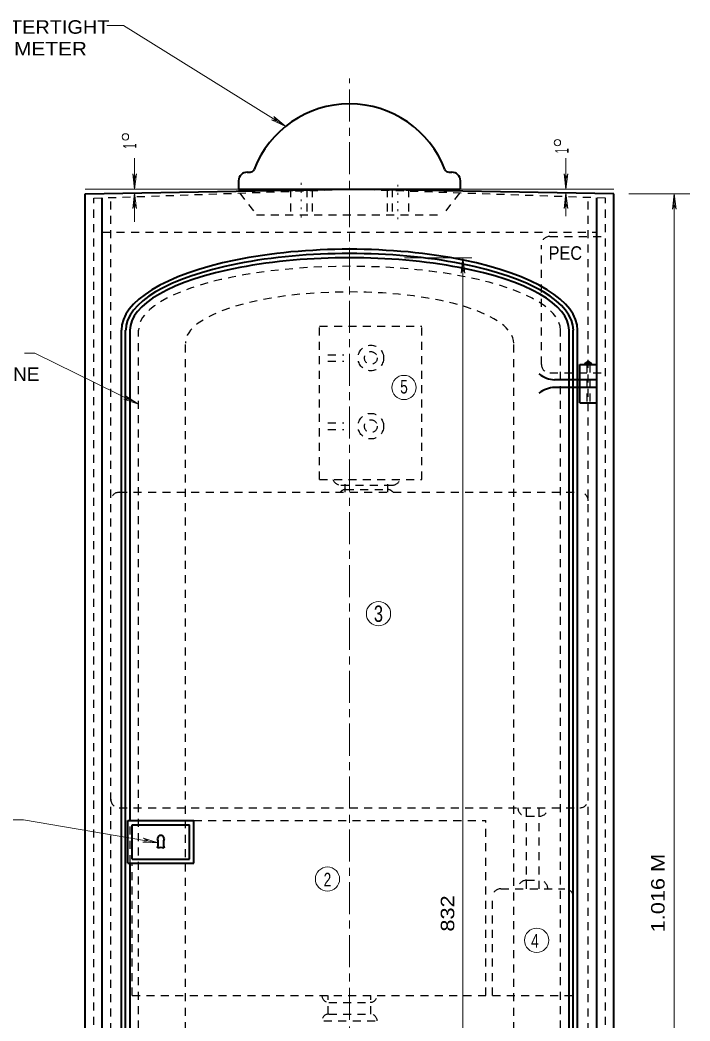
# Model space of a CAD drawing. Extents: x 312583 to 312853, y 144419 to 144586.
# Drawn here: x 312634.8 to 312672.5, y 144473.4 to 144529.6 of the extents above; entities that cross this region are included whole.
import ezdxf
from ezdxf.enums import TextEntityAlignment as Align

# ---------------------------------------------------------------- set-up
doc = ezdxf.new("R2010")
doc.units = 0
doc.header["$LTSCALE"] = 0.3
for name, pattern in [('DOTTED', [1.5, 0.3, -1.2]), ('LONG_DASH_SHORT_DASH', [9.9, 6, -1.2, 1.5, -1.2]), ('SHORT_DASHED', [2.7, 1.5, -1.2])]:
    doc.linetypes.add(name, pattern=pattern)
doc.layers.add('1', color=7, linetype='Continuous', lineweight=13)

msp = doc.modelspace()

# ---------------------------------------------------------------- linework, layer by layer
at = {"layer": '1', "linetype": 'LONG_DASH_SHORT_DASH'}
msp.add_line((312653.3356, 144440.7591), (312653.3356, 144526.3344), dxfattribs=at)
at = {"layer": '1'}
for p, q in [((312649.0729, 144524.1954), (312649.2493, 144523.9578)), ((312649.7476, 144523.6434), (312649.0729, 144524.1954)), ((312648.9579, 144524.0114), (312649.2493, 144523.9578)), ((312649.7476, 144523.6434), (312648.9579, 144524.0114)), ((312641.2606, 144520.1091), (312641.2606, 144521.8571)), ((312665.4949, 144520.1091), (312665.4949, 144521.8571)), ((312641.1533, 144520.9754), (312641.2606, 144520.6994)), ((312641.2606, 144520.1091), (312641.1533, 144520.9754)), ((312641.3679, 144520.9754), (312641.2606, 144520.6994)), ((312641.2606, 144520.1091), (312641.3679, 144520.9754)), ((312665.3876, 144520.9754), (312665.4949, 144520.6994)), ((312665.4949, 144520.1091), (312665.3876, 144520.9754)), ((312665.6023, 144520.9754), (312665.4949, 144520.6994)), ((312665.4949, 144520.1091), (312665.6023, 144520.9754)), ((312653.3356, 144520.1091), (312638.4776, 144520.1091)), ((312641.2606, 144519.8944), (312641.1533, 144519.0281)), ((312641.2606, 144518.2768), (312641.2606, 144519.8944)), ((312641.2606, 144519.8944), (312641.3679, 144519.0281)), ((312653.3356, 144520.1091), (312668.1859, 144520.1091)), ((312665.4949, 144519.8944), (312665.3876, 144519.0281)), ((312665.4949, 144518.5911), (312665.4949, 144519.8944)), ((312665.4949, 144519.8944), (312665.6023, 144519.0281)), ((312669.0369, 144519.8484), (312672.4653, 144519.8484)), ((312671.5823, 144519.8484), (312671.475, 144518.9821)), ((312671.5823, 144443.1818), (312671.5823, 144519.8484)), ((312671.5823, 144519.8484), (312671.6897, 144518.9821)), ((312641.1533, 144519.0281), (312641.2606, 144519.3041)), ((312641.3679, 144519.0281), (312641.2606, 144519.3041)), ((312665.3876, 144519.0281), (312665.4949, 144519.3041)), ((312665.6023, 144519.0281), (312665.4949, 144519.3041)), ((312671.475, 144518.9821), (312671.5823, 144519.2581)), ((312671.6897, 144518.9821), (312671.5823, 144519.2581)), ((312656.4329, 144516.2528), (312660.2049, 144516.2528)), ((312659.7066, 144516.2528), (312659.5993, 144515.3864)), ((312659.7066, 144462.9541), (312659.7066, 144516.2528)), ((312659.7066, 144516.2528), (312659.8139, 144515.3864)), ((312659.5993, 144515.3864), (312659.7066, 144515.6624)), ((312659.8139, 144515.3864), (312659.7066, 144515.6624)), ((312635.6486, 144510.8938), (312635.0712, 144510.8938)), ((312641.4753, 144508.0264), (312635.6486, 144510.8938)), ((312640.6549, 144508.3178), (312640.9463, 144508.2871)), ((312641.4753, 144508.0264), (312640.6549, 144508.3178)), ((312640.7469, 144508.5094), (312640.9463, 144508.2871)), ((312641.4753, 144508.0264), (312640.7469, 144508.5094)), ((312635.0199, 144484.6814), (312633.7017, 144484.6814)), ((312642.5869, 144483.3858), (312635.0199, 144484.6814)), ((312641.7513, 144483.6388), (312642.0043, 144483.4854)), ((312642.5869, 144483.3858), (312641.7513, 144483.6388)), ((312641.7206, 144483.4241), (312642.0043, 144483.4854)), ((312642.5869, 144483.3858), (312641.7206, 144483.4241))]:
    msp.add_line(p, q, dxfattribs=at)
at = {"layer": '1', "lineweight": 40}
for p, q in [((312647.5856, 144521.0674), (312647.7466, 144521.0674)), ((312658.9246, 144521.0674), (312659.0856, 144521.0674)), ((312647.1026, 144520.5844), (312647.1026, 144520.1091)), ((312659.5609, 144520.5844), (312659.5609, 144520.1091)), ((312638.4776, 144519.8484), (312653.3356, 144520.1091)), ((312638.4776, 144444.8608), (312638.4776, 144519.8484)), ((312639.4359, 144449.6524), (312639.4359, 144519.6261)), ((312647.1026, 144520.1091), (312659.5609, 144520.1091)), ((312647.1026, 144520.1091), (312659.5609, 144520.1091)), ((312668.1859, 144519.8484), (312653.3356, 144520.1091)), ((312667.2276, 144449.6524), (312667.2276, 144519.6261)), ((312668.1859, 144444.8608), (312668.1859, 144519.8484)), ((312640.5169, 144454.6818), (312640.5169, 144512.1818)), ((312640.7546, 144454.6818), (312640.7546, 144512.1818)), ((312640.9999, 144484.6278), (312640.9999, 144512.1818)), ((312665.6713, 144457.5568), (312665.6713, 144512.1818)), ((312665.9089, 144454.6818), (312665.9089, 144512.1818)), ((312666.1543, 144454.6818), (312666.1543, 144512.1818)), ((312666.2693, 144510.2651), (312667.2276, 144510.2651)), ((312666.2693, 144508.1108), (312666.2693, 144510.2651)), ((312667.2046, 144509.4064), (312664.8586, 144509.4064)), ((312667.2046, 144508.9694), (312664.8586, 144508.9694)), ((312666.2693, 144508.1108), (312667.2276, 144508.1108)), ((312640.8773, 144484.6278), (312644.5879, 144484.6278)), ((312640.8773, 144482.2358), (312640.8773, 144484.6278)), ((312641.1149, 144484.3901), (312644.3503, 144484.3901)), ((312641.1149, 144482.4734), (312641.1149, 144484.3901)), ((312644.3503, 144482.4734), (312644.3503, 144484.3901)), ((312644.5879, 144482.2358), (312644.5879, 144484.6278)), ((312641.1149, 144482.4734), (312644.3503, 144482.4734)), ((312640.8773, 144482.2358), (312644.5879, 144482.2358)), ((312640.9999, 144457.5568), (312640.9999, 144482.2358))]:
    msp.add_line(p, q, dxfattribs=at)
at = {"layer": '1', "linetype": 'DOTTED'}
for p, q in [((312650.6216, 144520.4618), (312650.6216, 144518.2844)), ((312656.0419, 144520.3621), (312656.0419, 144518.2844))]:
    msp.add_line(p, q, dxfattribs=at)
at = {"layer": '1', "linetype": 'SHORT_DASHED', "lineweight": 25}
for p, q in [((312638.9606, 144519.6108), (312653.3356, 144520.1091)), ((312638.9606, 144443.1818), (312638.9606, 144519.6108)), ((312639.9189, 144450.1278), (312639.9189, 144519.6414)), ((312647.1639, 144519.8944), (312648.1069, 144518.6678)), ((312650.0236, 144520.1091), (312650.0236, 144518.6678)), ((312650.9359, 144520.1091), (312650.9359, 144518.6678)), ((312651.2273, 144520.1091), (312651.2273, 144518.6678)), ((312667.7106, 144519.6108), (312653.3356, 144520.1091)), ((312655.4439, 144520.1091), (312655.4439, 144518.6678)), ((312655.7276, 144520.1091), (312655.7276, 144518.6678)), ((312656.6476, 144520.1091), (312656.6476, 144518.6678)), ((312659.5073, 144519.8944), (312658.5643, 144518.6678)), ((312666.7523, 144450.1278), (312666.7523, 144519.6414)), ((312667.7106, 144443.1818), (312667.7106, 144519.6108)), ((312648.1069, 144518.6678), (312658.5643, 144518.6678)), ((312639.4359, 144517.6941), (312667.2276, 144517.6941)), ((312664.5979, 144517.4564), (312667.7106, 144517.4564)), ((312664.1149, 144510.2651), (312664.1149, 144516.9734)), ((312651.6566, 144512.4194), (312657.4066, 144512.4194)), ((312651.6566, 144503.7944), (312651.6566, 144512.4194)), ((312657.4066, 144503.7944), (312657.4066, 144512.4194)), ((312641.4753, 144457.5568), (312641.4753, 144512.1818)), ((312665.1959, 144457.5568), (312665.1959, 144512.1818)), ((312644.1126, 144458.2774), (312644.1126, 144511.4611)), ((312662.5586, 144458.2774), (312662.5586, 144511.4611)), ((312652.1243, 144510.8094), (312653.0136, 144510.8094)), ((312652.1243, 144510.4491), (312653.0136, 144510.4491)), ((312666.6603, 144510.2574), (312666.6603, 144508.1031)), ((312666.8443, 144510.2574), (312666.8443, 144508.1031)), ((312664.5979, 144509.7898), (312667.7106, 144509.7898)), ((312652.1243, 144506.9761), (312653.0136, 144506.9761)), ((312652.1243, 144506.6158), (312653.0136, 144506.6158)), ((312651.6566, 144503.7944), (312657.4066, 144503.7944)), ((312652.8526, 144503.4801), (312655.7276, 144503.4801)), ((312653.0979, 144503.0814), (312653.0979, 144503.7944)), ((312655.4899, 144503.0814), (312655.4899, 144503.7944)), ((312640.3943, 144503.0814), (312666.2693, 144503.0814)), ((312653.1286, 144503.2424), (312655.4593, 144503.2424)), ((312640.3943, 144485.3484), (312666.2693, 144485.3484)), ((312663.2793, 144480.7944), (312663.2793, 144485.3484)), ((312663.9999, 144480.7944), (312663.9999, 144485.3484)), ((312663.2793, 144484.8731), (312663.9999, 144484.8731)), ((312640.9999, 144482.2358), (312640.9999, 144484.6278)), ((312644.5879, 144484.6278), (312661.0023, 144484.6278)), ((312641.1149, 144474.8068), (312641.1149, 144482.2358)), ((312661.8379, 144480.7944), (312665.4336, 144480.7944)), ((312663.2793, 144481.2774), (312663.9999, 144481.2774)), ((312661.3626, 144474.8068), (312661.3626, 144480.3191)), ((312652.1396, 144473.7564), (312652.1396, 144474.8068)), ((312654.5316, 144473.7564), (312654.5316, 144474.8068)), ((312661.3626, 144474.8068), (312665.9166, 144474.8068)), ((312652.1703, 144474.4158), (312654.5009, 144474.4158)), ((312652.1703, 144473.7564), (312654.5009, 144473.7564)), ((312651.8943, 144473.3731), (312654.7693, 144473.3731))]:
    msp.add_line(p, q, dxfattribs=at)
at = {"layer": '1'}
msp.add_lwpolyline([(312649.7476, 144523.6434), (312640.6396, 144529.3014), (312639.6963, 144529.3014)], dxfattribs=at)
at = {"layer": '1', "linetype": 'SHORT_DASHED', "lineweight": 25}
msp.add_lwpolyline([(312641.1149, 144474.8068), (312661.0023, 144474.8068), (312661.0023, 144484.6278)], dxfattribs=at)
at = {"layer": '1'}
for centre, radius in [((312640.7432, 144523.051), 0.1797), ((312665.0178, 144522.7251), 0.1797), ((312656.3965, 144508.9694), 0.6818), ((312654.9629, 144496.2581), 0.6818), ((312652.0955, 144481.3464), 0.6818), ((312663.8524, 144477.906), 0.6818)]:
    msp.add_circle(centre, radius, dxfattribs=at)
at = {"layer": '1', "linetype": 'SHORT_DASHED', "lineweight": 25}
for centre, radius in [((312654.5316, 144510.6274), 0.7188), ((312654.5316, 144510.6274), 0.3594), ((312654.5316, 144506.794), 0.7188), ((312654.5316, 144506.794), 0.3594)]:
    msp.add_circle(centre, radius, dxfattribs=at)
at = {"layer": '1', "lineweight": 40}
for centre, radius, start, end in [((312653.3337, 144519.1508), 5.75, 21.1002, 158.90079), ((312647.5837, 144520.5883), 0.4792, 90, 180), ((312647.7457, 144521.307), 0.2396, 270, 338.8998), ((312658.9217, 144521.307), 0.2396, 201.1002, 270), ((312659.0837, 144520.5883), 0.4792, 0, 90), ((312666.7517, 144510.2221), 0.1954, 17.35766, 165.56497), ((312666.7499, 144510.2338), 0.1465, 17.35766, 165.56497), ((312666.7501, 144510.2455), 0.0977, 17.35766, 165.56497), ((312666.746, 144510.2631), 0.0244, 17.35766, 165.56497), ((312664.9241, 144510.9283), 1.5233, 231.73709, 267.53516), ((312664.9241, 144507.4494), 1.5233, 92.46484, 128.26291), ((312642.7345, 144483.6177), 0.184, 0.60951, 179.40319), ((312641.6434, 144483.348), 0.9469, 343.7422, 16.66705), ((312643.8218, 144483.348), 0.9469, 163.33295, 196.2578), ((312642.7326, 144482.6555), 0.4638, 67.14337, 112.85662)]:
    msp.add_arc(centre, radius, start, end, dxfattribs=at)
at = {"layer": '1', "linetype": 'SHORT_DASHED', "lineweight": 25}
for centre, radius, start, end in [((312664.5941, 144516.9754), 0.4792, 90, 180), ((312664.5941, 144510.267), 0.4792, 180, 270), ((312652.8545, 144503.9612), 0.4792, 199.98311, 270), ((312655.7295, 144503.9612), 0.4792, 270, 340.11484), ((312640.3962, 144502.6004), 0.4792, 90, 180), ((312653.1287, 144502.8541), 0.3881, 90.0198, 144.53298), ((312655.4575, 144502.8541), 0.3881, 35.49, 90.0198), ((312666.2712, 144502.6004), 0.4792, 0, 90), ((312640.3962, 144485.8295), 0.4792, 180, 270), ((312666.2712, 144485.8295), 0.4792, 270, 0), ((312663.2773, 144485.3523), 0.4792, 180, 270), ((312663.9961, 144485.3523), 0.4792, 270, 0), ((312661.8398, 144480.3191), 0.4792, 90, 180), ((312663.2773, 144480.7983), 0.4792, 90, 180), ((312663.9961, 144480.7983), 0.4792, 0, 90), ((312665.4355, 144480.3191), 0.4792, 0, 90), ((312652.1704, 144474.8079), 0.3881, 180, 270), ((312654.4992, 144474.8079), 0.3881, 270, 0), ((312652.1704, 144473.372), 0.3881, 90, 180), ((312654.4992, 144473.372), 0.3881, 0, 90)]:
    msp.add_arc(centre, radius, start, end, dxfattribs=at)
at = {"layer": '1', "lineweight": 40}
for major_axis, ratio in [((12.8177, 0), 0.35514), ((12.5781, 0), 0.342857), ((12.3385, 0), 0.330097)]:
    msp.add_ellipse((312653.3346, 144512.1837), major_axis=major_axis, ratio=ratio, start_param=6.2831853, end_param=9.424778, dxfattribs=at)
at = {"layer": '1', "linetype": 'SHORT_DASHED', "lineweight": 25}
for centre, major_axis, ratio, start_param, end_param in [((312653.3346, 144512.1837), (11.8594, 0), 0.30303, 6.2831853, 9.424778), ((312653.3346, 144511.4649), (-9.224, 0), 0.311688, 3.1415927, 6.2831853)]:
    msp.add_ellipse(centre, major_axis=major_axis, ratio=ratio, start_param=start_param, end_param=end_param, dxfattribs=at)

# ---------------------------------------------------------------- texts
at = {"layer": '1'}
for s, width, p in [('PROVIDE APPROVED WATERTIGHT', 1.1, (312620.5885, 144528.8469)), ('COVER (SEE DETAIL OF METER', 1.15, (312620.5885, 144527.6269)), ('PEC', 0.9, (312664.5213, 144516.1444)), ('WITH CONTINUOUS NEOPRENE', 1.05, (312619.4332, 144509.3354)), ('5', 0.75, (312656.1845, 144508.6304)), ('2', 0.75, (312651.8835, 144480.9372)), ('4', 0.75, (312663.5391, 144477.495))]:
    msp.add_text(s, height=0.76, dxfattribs=dict(at, width=width)).set_placement(p)
for s, width, p in [('1', 0.5, (312641.3594, 144522.4014)), ('1', 0.5, (312665.6397, 144522.1254)), ('1.016 M', 1.2, (312671.0415, 144478.3546)), ('832 ', 1.2, (312659.2217, 144478.3954))]:
    msp.add_text(s, height=0.76, rotation=90, dxfattribs=dict(at, width=width)).set_placement(p)
at = {"layer": '1', "width": 0.75}
msp.add_text('3', height=0.92, dxfattribs=at).set_placement((312654.9609, 144495.7981), align=Align.CENTER)

doc.saveas('drawing.dxf')
